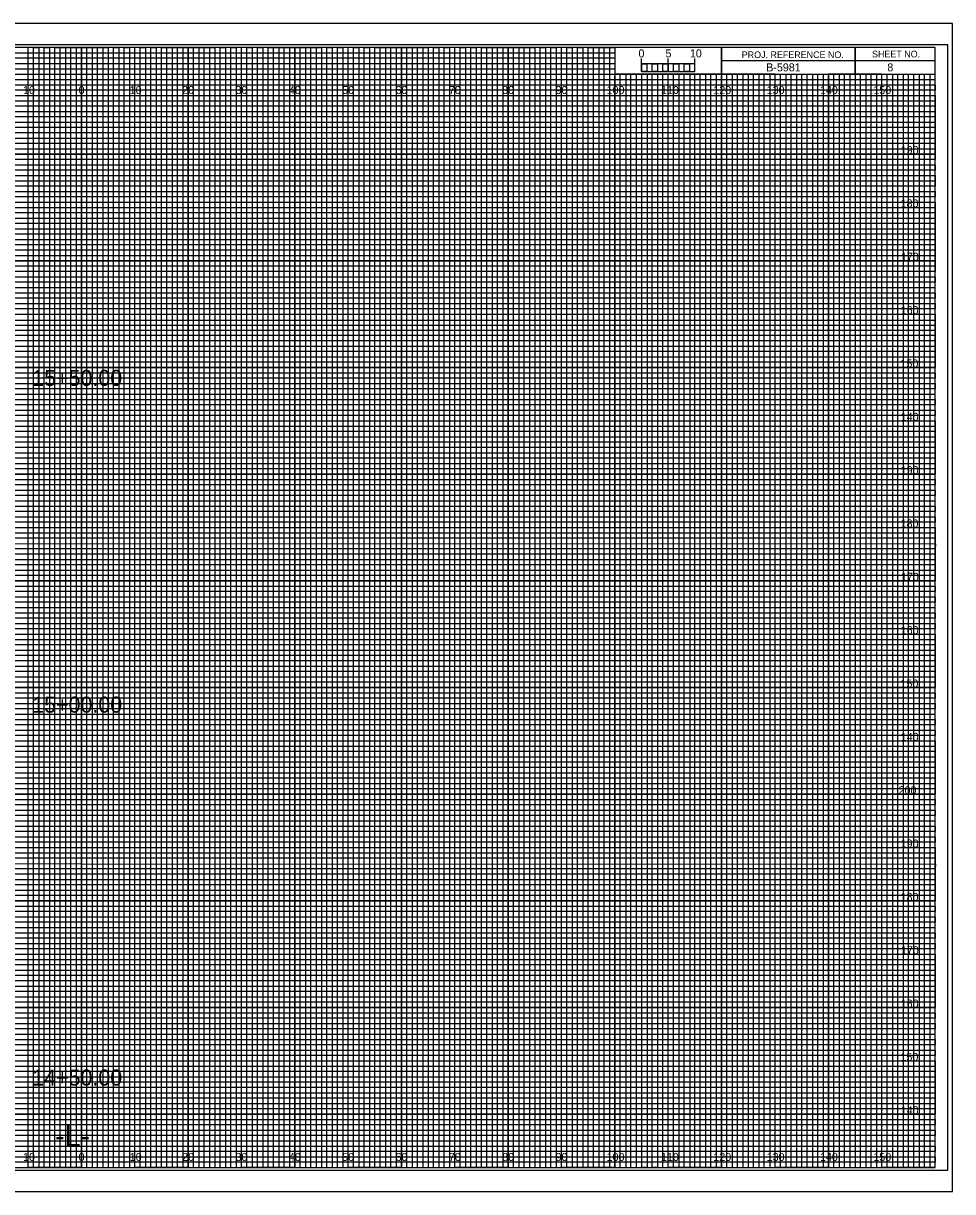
# Model space of a CAD drawing. Extents: x -13 to 323, y -5 to 4174.
# Drawn here: x 149.1 to 323.3, y 435.5 to 654.5 of the extents above; entities that cross this region are included whole.
import ezdxf

# ---------------------------------------------------------------- set-up
doc = ezdxf.new("R2010")
doc.units = 0
for name, color, linetype in [('Exist Cross Section Cell', 7, 'Continuous'), ('Exist XS Center Line Elevation Label', 7, 'Continuous'), ('Exist XS Ground Line', 7, 'Continuous'), ('Prop CMT Concrete Structures', 7, 'Continuous'), ('Prop CMT Guardrail Graphics', 7, 'Continuous'), ('Prop CMT Pvmt Course 1', 7, 'Continuous'), ('Prop CMT Pvmt Course 2', 7, 'Continuous'), ('Prop CMT Pvmt Course 3', 7, 'Continuous'), ('Prop CMT Pvmt Surface', 7, 'Continuous'), ('Prop CMT Shld Paved Course 1', 7, 'Continuous'), ('Prop CMT Shld Paved Course 2', 7, 'Continuous'), ('Prop CMT Shld Paved Course 3', 7, 'Continuous'), ('Prop CMT Subgrade Earthwork', 7, 'Continuous'), ('Prop XS Ditch Standard Text', 7, 'Continuous'), ('Prop XS SE Text', 7, 'Continuous'), ('Prop XS Side Slope Text', 7, 'Continuous'), ('Scratch_Level_0', 7, 'Continuous')]:
    doc.layers.add(name, color=color, linetype=linetype)

msp = doc.modelspace()

# ---------------------------------------------------------------- linework, layer by layer
at = {"layer": 'Exist XS Center Line Elevation Label'}
for points in [[(145, 440), (155, 440), (155, 650), (165, 650), (165, 440), (175, 440), (175, 650), (185, 650), (185, 440), (195, 440), (195, 650), (205, 650), (205, 440), (215, 440), (215, 650), (225, 650), (225, 440), (235, 440), (235, 650), (245, 650), (245, 440), (255, 440), (255, 650), (259.93, 650), (260, 650), (260, 645), (264.99, 645), (264.99, 440), (275, 440), (275, 645), (285, 645), (285, 440), (295, 440), (295, 645), (305, 645), (305, 440), (315, 440), (315, 645)], [(0, 645), (275, 645)], [(0, 625), (320, 625), (320, 635), (0, 635)], [(0, 605), (320, 605), (320, 615), (0, 615)], [(0, 585), (320, 585), (320, 595), (0, 595)], [(0, 565), (320, 565), (320, 575), (0, 575)], [(0, 545), (320, 545), (320, 555), (0, 555)], [(0, 525), (320, 525), (320, 535), (0, 535)], [(0, 505), (320, 505), (320, 515), (0, 515)], [(0, 485), (320, 485), (320, 495), (0, 495)], [(0, 465), (320, 465), (320, 475), (0, 475)], [(0, 445), (320, 445), (320, 455), (0, 455)]]:
    msp.add_lwpolyline(points, dxfattribs=at)
at = {"layer": 'Exist XS Ground Line'}
for p, q in [((150, 650), (140, 650)), ((150, 440), (150, 650)), ((170, 650), (160, 650)), ((160, 650), (160, 440)), ((170, 440), (170, 650)), ((190, 650), (180, 650)), ((180, 650), (180, 440)), ((190, 440), (190, 650)), ((210, 650), (200, 650)), ((200, 650), (200, 440)), ((210, 440), (210, 650)), ((230, 650), (220, 650)), ((220, 650), (220, 440)), ((230, 440), (230, 650)), ((250, 650), (240, 650)), ((240, 650), (240, 440)), ((250, 440), (250, 650)), ((260, 650), (260, 440)), ((270, 440), (270, 645)), ((290, 645), (280, 645)), ((280, 645), (280, 440)), ((290, 440), (290, 645)), ((310, 645), (300, 645)), ((300, 645), (300, 440)), ((310, 440), (310, 645)), ((160, 440), (150, 440)), ((180, 440), (170, 440)), ((200, 440), (190, 440)), ((220, 440), (210, 440)), ((240, 440), (230, 440)), ((260, 440), (250, 440)), ((280, 440), (270, 440)), ((300, 440), (290, 440)), ((320, 440), (310, 440)), ((320, 440), (320, 440))]:
    msp.add_line(p, q, dxfattribs=at)
for points in [[(0, 640), (320, 640), (320, 630), (0, 630)], [(0, 620), (320, 620), (320, 610), (0, 610)], [(0, 600), (320, 600), (320, 590), (0, 590)], [(0, 580), (320, 580), (320, 570), (0, 570)], [(0, 560), (320, 560), (320, 550), (0, 550)], [(0, 540), (320, 540), (320, 530), (0, 530)], [(0, 520), (320, 520), (320, 510), (0, 510)], [(0, 500), (320, 500), (320, 490), (0, 490)], [(0, 480), (320, 480), (320, 470), (0, 470)], [(0, 460), (320, 460), (320, 450), (0, 450)]]:
    msp.add_lwpolyline(points, dxfattribs=at)
at = {"layer": 'Prop CMT Pvmt Course 1'}
for p, q in [((323.3, 654.5), (-13.4, 654.5)), ((-13.4, 435.5), (323.3, 435.5))]:
    msp.add_line(p, q, dxfattribs=at)
at = {"layer": 'Prop CMT Pvmt Course 2'}
msp.add_lwpolyline([(-13.4, 435.5), (323.3, 435.5), (323.3, 654.5), (-13.4, 654.5)], close=True, dxfattribs=at)
at = {"layer": 'Prop CMT Pvmt Course 3'}
msp.add_lwpolyline([(-10.8, 439.5), (322.4, 439.5), (322.4, 650.5), (-10.8, 650.5)], close=True, dxfattribs=at)
at = {"layer": 'Prop CMT Shld Paved Course 1'}
for p, q in [((305, 650), (305, 645)), ((305, 645), (305, 650)), ((280, 647.5), (280, 645)), ((320, 647.49), (280, 647.49)), ((280, 645), (320, 645))]:
    msp.add_line(p, q, dxfattribs=at)
for points in [[(320, 650), (0, 650), (0, 440), (320, 440)], [(280, 650), (260, 650), (260, 645.03), (280, 645.03)], [(320, 650), (280, 650), (280, 645), (320, 645)]]:
    msp.add_lwpolyline(points, close=True, dxfattribs=at)
at = {"layer": 'Prop CMT Shld Paved Course 2'}
for p, q in [((267, 645), (266.01, 645)), ((266.01, 645), (266.01, 440)), ((267, 440), (267, 645)), ((269, 645), (268, 645)), ((268, 645), (268, 440)), ((269, 440), (269, 645)), ((266.01, 440), (265, 440)), ((268, 440), (267, 440))]:
    msp.add_line(p, q, dxfattribs=at)
for points in [[(150, 440), (151, 440), (151, 650), (152, 650), (152, 440)], [(152, 440), (153, 440), (153, 650), (154, 650), (154, 440)], [(155, 440), (156, 440), (156, 650), (157, 650), (157, 440)], [(157, 440), (158, 440), (158, 650), (159, 650), (159, 440)], [(160, 440), (161, 440), (161, 650), (162, 650), (162, 440)], [(162, 440), (163, 440), (163, 650), (164, 650), (164, 440)], [(165, 440), (166, 440), (166, 650), (167, 650), (167, 440)], [(167, 440), (168, 440), (168, 650), (169, 650), (169, 440)], [(170, 440), (171, 440), (171, 650), (172, 650), (172, 440)], [(172, 440), (173, 440), (173, 650), (174, 650), (174, 440)], [(175, 440), (176, 440), (176, 650), (177, 650), (177, 440)], [(177, 440), (178, 440), (178, 650), (179, 650), (179, 440)], [(180, 440), (181, 440), (181, 650), (182, 650), (182, 440)], [(182, 440), (183, 440), (183, 650), (184, 650), (184, 440)], [(185, 440), (186, 440), (186, 650), (187, 650), (187, 440)], [(187, 440), (188, 440), (188, 650), (189, 650), (189, 440)], [(190, 440), (191, 440), (191, 650), (192, 650), (192, 440)], [(192, 440), (193, 440), (193, 650), (194, 650), (194, 440)], [(195, 440), (196, 440), (196, 650), (197, 650), (197, 440)], [(197, 440), (198, 440), (198, 650), (199, 650), (199, 440)], [(200, 440), (201, 440), (201, 650), (202, 650), (202, 440)], [(202, 440), (203, 440), (203, 650), (204, 650), (204, 440)], [(205, 440), (206, 440), (206, 650), (207, 650), (207, 440)], [(207, 440), (208, 440), (208, 650), (209, 650), (209, 440)], [(210, 440), (211, 440), (211, 650), (212, 650), (212, 440)], [(212, 440), (213, 440), (213, 650), (214, 650), (214, 440)], [(215, 440), (216, 440), (216, 650), (217, 650), (217, 440)], [(217, 440), (218, 440), (218, 650), (219, 650), (219, 440)], [(220, 440), (221, 440), (221, 650), (222, 650), (222, 440)], [(222, 440), (223, 440), (223, 650), (224, 650), (224, 440)], [(225, 440), (226, 440), (226, 650), (227, 650), (227, 440)], [(227, 440), (228, 440), (228, 650), (229, 650), (229, 440)], [(230, 440), (231, 440), (231, 650), (232, 650), (232, 440)], [(232, 440), (233, 440), (233, 650), (234, 650), (234, 440)], [(235, 440), (236, 440), (236, 650), (237, 650), (237, 440)], [(237, 440), (238, 440), (238, 650), (239, 650), (239, 440)], [(240, 440), (241, 440), (241, 650), (242, 650), (242, 440)], [(242, 440), (243, 440), (243, 650), (244, 650), (244, 440)], [(245, 440), (246, 440), (246, 650), (247, 650), (247, 440)], [(247, 440), (248, 440), (248, 650), (249, 650), (249, 440)], [(250, 440), (251, 440), (251, 650), (252, 650), (252, 440)], [(252, 440), (253, 440), (253, 650), (254, 650), (254, 440)], [(255, 440), (256, 440), (256, 650), (257, 650), (257, 440)], [(257, 440), (258, 440), (258, 650), (259, 650), (259, 440)], [(260, 440), (261, 440), (261, 645), (262.02, 645), (262.02, 440)], [(262, 440), (263, 440), (263, 645), (263.99, 645), (263.99, 440)], [(270, 440), (270.98, 440), (270.98, 645), (272, 645), (272, 440)], [(272, 440), (273, 440), (273, 645), (274.05, 645), (274.05, 440)], [(275, 440), (276, 440), (276, 645), (277, 645), (277, 440)], [(277, 440), (278, 440), (278, 645), (279, 645), (279, 440)], [(280, 440), (281, 440), (281, 645), (282, 645), (282, 440)], [(282, 440), (283, 440), (283, 645), (284, 645), (284, 440)], [(285, 440), (286, 440), (286, 645), (287, 645), (287, 440)], [(287, 440), (288, 440), (288, 645), (289, 645), (289, 440)], [(290, 440), (291, 440), (291, 645), (292, 645), (292, 440)], [(292, 440), (293, 440), (293, 645), (294, 645), (294, 440)], [(295, 440), (296, 440), (296, 645), (297, 645), (297, 440)], [(297, 440), (298, 440), (298, 645), (299, 645), (299, 440)], [(300, 440), (301, 440), (301, 645), (302, 645), (302, 440)], [(302, 440), (303, 440), (303, 645), (304, 645), (304, 440)], [(305, 440), (306, 440), (306, 645), (307, 645), (307, 440)], [(307, 440), (308, 440), (308, 645), (309, 645), (309, 440)], [(310, 440), (311, 440), (311, 645), (312, 645), (312, 440)], [(312, 440), (313, 440), (313, 645), (314, 645), (314, 440)], [(315, 440), (316, 440), (316, 645), (317, 645), (317, 440)], [(317, 440), (318, 440), (318, 645), (319, 645), (319, 440)]]:
    msp.add_lwpolyline(points, dxfattribs=at)
at = {"layer": 'Prop CMT Shld Paved Course 3'}
for p, q in [((265, 645.49), (265, 647.9)), ((265, 646.9), (265, 647.9)), ((270, 645.49), (270, 647.9)), ((275, 645.49), (275, 647.9)), ((275, 646.9), (275, 647.9))]:
    msp.add_line(p, q, dxfattribs=at)
for points in [[(275, 646.9), (265, 646.9), (265, 645.49), (275, 645.49)], [(265, 646.9), (266, 646.9), (266, 645.49), (265, 645.49)], [(267, 646.9), (268, 646.9), (268, 645.49), (267, 645.49)], [(269, 646.9), (270, 646.9), (270, 645.49), (269, 645.49)], [(271, 646.9), (272, 646.9), (272, 645.49), (271, 645.49)], [(273, 646.9), (274, 646.9), (274, 645.49), (273, 645.49)]]:
    msp.add_lwpolyline(points, close=True, dxfattribs=at)
at = {"layer": 'Prop CMT Subgrade Earthwork'}
for p, q in [((150, 440), (150, 650)), ((160, 440), (160, 650)), ((170, 440), (170, 650)), ((180, 440), (180, 650)), ((190, 440), (190, 650)), ((200, 440), (200, 650)), ((210, 440), (210, 650)), ((220, 440), (220, 650)), ((230, 440), (230, 650)), ((240, 440), (240, 650)), ((250, 440), (250, 650)), ((260, 440), (260, 644.69)), ((270, 440), (270, 644.69)), ((280, 440), (280, 644.69)), ((290, 440), (290, 644.69)), ((300, 440), (300, 644.69)), ((310, 440), (310, 644.69)), ((0, 640), (320, 640)), ((0, 630), (320, 630)), ((0, 620), (320, 620)), ((0, 610), (320, 610)), ((0, 600), (320, 600)), ((0, 590), (320, 590)), ((0, 580), (320, 580)), ((0, 570), (320, 570)), ((0, 560), (320, 560)), ((0, 550), (320, 550)), ((0, 540), (320, 540)), ((0, 530), (320, 530)), ((0, 520), (320, 520)), ((0, 510), (320, 510)), ((0, 500), (320, 500)), ((0, 490), (320, 490)), ((0, 480), (320, 480)), ((0, 470), (320, 470)), ((0, 460), (320, 460)), ((0, 450), (320, 450))]:
    msp.add_line(p, q, dxfattribs=at)
at = {"layer": 'Scratch_Level_0'}
for p, q in [((0, 649), (260, 649)), ((260, 649), (260, 647.98)), ((260, 647.98), (0, 647.98)), ((0, 647), (260, 647)), ((260, 647), (260, 645.89)), ((260, 645.89), (0, 645.89)), ((0, 644), (320, 644))]:
    msp.add_line(p, q, dxfattribs=at)
for points in [[(0, 643), (270, 643), (320, 643), (320, 642), (0, 642)], [(0, 641), (320, 641), (320, 639), (0, 639)], [(0, 638), (320, 638), (320, 637), (0, 636.98)], [(0, 636), (320, 636), (320, 634), (0, 634)], [(0, 633), (320, 633), (320, 632), (0, 632)], [(0, 631), (320, 631), (320, 629), (0, 629)], [(0, 628), (320, 628), (320, 627), (0, 627)], [(0, 626), (320, 626), (320, 624), (0, 624)], [(0, 623), (320, 623), (320, 622), (0, 622)], [(0, 621), (320, 621), (320, 619), (0, 619)], [(0, 618), (320, 618), (320, 617), (0, 617)], [(0, 616), (320, 616), (320, 613.95), (320, 613), (320, 612), (0, 612)], [(0, 614), (320, 614), (320, 613), (0, 613)], [(0, 611), (320, 611), (320, 609), (0, 609.03)], [(0, 609.03), (320, 609), (320, 608), (0, 608)], [(0, 607), (320, 607), (320, 606), (0, 606)], [(0, 604), (320, 604), (320, 603), (0, 603)], [(0, 602), (320, 602), (320, 601), (0, 601)], [(-0.07, 598.89), (320, 598.89), (320, 597.88), (-0.07, 597.88)], [(0, 597), (320, 597), (320, 596), (0, 596)], [(0, 594), (320, 594), (320, 593), (0, 593)], [(0, 592), (320, 592), (320, 591), (0, 591)], [(0, 589), (320, 589), (320, 588), (0, 588)], [(0, 587), (320, 587), (320, 586), (0, 586)], [(0, 584), (320, 584), (320, 583), (0, 583)], [(0, 582), (320, 582), (320, 581), (0, 581)], [(0, 579), (320, 579), (319.99, 577.98), (0, 578)], [(0, 577), (320, 577), (320, 576), (0, 576)], [(0, 574), (320, 574), (320, 573), (0, 573)], [(0, 572), (320, 572), (320, 571), (0, 571)], [(0, 569), (320, 569), (320, 568), (0, 568)], [(0, 567), (320, 567), (320, 566), (0, 566)], [(0, 564), (320, 564), (320, 563), (0, 563)], [(0, 562), (320, 562), (320, 561), (0, 561)], [(0, 559), (320, 559), (320, 558), (0, 558)], [(0, 556.99), (320.07, 556.91), (320, 556), (0, 556)], [(0, 554), (320, 554), (320, 553), (0, 553)], [(0, 552), (320, 552), (320, 551), (0, 551)], [(0, 549), (320, 549), (320, 548), (0, 548)], [(0, 547), (320, 547), (320, 546), (0, 546)], [(0, 544), (320, 544), (320, 543), (0, 543)], [(0, 542), (320, 542), (320, 541), (0, 541)], [(0, 539), (320, 539), (320, 538), (0, 538)], [(0, 537), (320, 537), (320, 536), (0, 536)], [(0, 534), (320, 534), (320, 533), (0, 533)], [(0, 532), (320, 532), (320, 531), (0, 531)], [(0, 529), (320, 529), (320, 528), (0, 528)], [(0, 527), (320, 527), (320, 526), (0, 526)], [(0, 524), (320, 524), (320, 523), (0, 523)], [(0, 522), (320, 522), (320, 521), (0, 521)], [(0, 519), (320, 519), (319.99, 517.98), (0, 518)], [(0, 517), (320, 517), (320, 516), (0, 516)], [(0, 514), (320, 514), (320, 513), (0, 513)], [(0, 512), (320, 512), (320, 511), (0, 511)], [(0, 509), (320, 509), (320, 508), (0, 508)], [(0, 507), (320, 507), (320, 506), (0, 506)], [(0, 504), (320, 504), (320, 503), (0, 503)], [(0, 502), (320, 502), (320, 501), (0, 501)], [(0, 499), (320, 499), (320, 498), (0, 498)], [(0, 496.99), (320.07, 496.91), (320, 496), (0, 496)], [(0, 494), (320, 494), (320, 493), (0, 493)], [(0, 492), (320, 492), (320, 491), (0, 491)], [(0, 489), (320, 489), (320, 488), (0, 488)], [(0, 487), (320, 487), (320, 486), (0, 486)], [(0, 484), (320, 484), (320, 483), (0, 483)], [(0, 482), (320, 482), (320, 481), (0, 481)], [(0, 479), (320, 479), (320, 478), (0, 478)], [(0, 477), (320, 477), (320, 476), (0, 476)], [(0, 474), (320, 474), (320, 473), (0, 473)], [(0, 472), (320, 472), (320, 471), (0, 471)], [(0, 469), (320, 469), (320, 468), (0, 468)], [(0, 467), (320, 467), (320, 466), (0, 466)], [(0, 464), (320, 464), (320, 463), (0, 463)], [(0, 462), (320, 462), (320, 461), (0, 461)], [(0, 459), (320, 459), (320, 458), (0, 458)], [(0, 457), (320, 457), (320, 456), (0, 456)], [(0, 454), (320, 454), (320, 453), (0, 453)], [(0, 452), (320, 452), (320, 451), (0, 451)], [(0, 449), (320, 449), (320, 448), (0, 448)], [(0, 447), (320, 447), (320, 446), (0, 446)], [(0, 444), (320, 444), (320, 443), (0, 443)], [(0, 442), (320, 442), (320, 441), (0, 441)]]:
    msp.add_lwpolyline(points, dxfattribs=at)

# ---------------------------------------------------------------- texts
at = {"layer": 'Exist Cross Section Cell'}
for s, p in [('10', (149.04, 641.25)), ('0', (159.45, 641.25)), ('0', (159.45, 641.25)), ('10', (169.04, 641.25)), ('20', (178.86, 641.25)), ('30', (188.86, 641.25)), ('40', (198.86, 641.25)), ('50', (208.86, 641.25)), ('60', (218.86, 641.25)), ('70', (228.86, 641.25)), ('80', (238.86, 641.25)), ('90', (248.86, 641.25)), ('100', (258.44, 641.25)), ('110', (268.62, 641.25)), ('120', (278.44, 641.25)), ('130', (288.44, 641.25)), ('140', (298.44, 641.25)), ('150', (308.44, 641.25)), ('10', (149.04, 441.25)), ('0', (159.45, 441.25)), ('0', (159.45, 441.25)), ('10', (169.04, 441.25)), ('20', (178.86, 441.25)), ('30', (188.86, 441.25)), ('40', (198.86, 441.25)), ('50', (208.86, 441.25)), ('60', (218.86, 441.25)), ('70', (228.86, 441.25)), ('80', (238.86, 441.25)), ('90', (248.86, 441.25)), ('100', (258.44, 441.25)), ('110', (268.62, 441.25)), ('120', (278.44, 441.25)), ('130', (288.44, 441.25)), ('140', (298.44, 441.25)), ('150', (308.44, 441.25))]:
    msp.add_text(s, height=1.5, dxfattribs=at).set_placement(p)
at = {"layer": 'Prop CMT Concrete Structures'}
for s, p in [('15+50.00', (150.77, 586.54)), ('15+00.00', (150.77, 525.29)), ('14+50.00', (150.77, 455.39))]:
    msp.add_text(s, height=3, dxfattribs=at).set_placement(p)
at = {"layer": 'Prop CMT Guardrail Graphics'}
for s, p in [('190', (313.57, 630)), ('180', (313.55, 620)), ('170', (313.61, 610)), ('160', (313.57, 600)), ('150', (313.52, 590)), ('140', (313.57, 580)), ('190', (313.57, 570)), ('180', (313.55, 560)), ('170', (313.61, 550)), ('160', (313.57, 540)), ('150', (313.52, 530)), ('140', (313.57, 520)), ('200', (313.17, 510)), ('190', (313.57, 500)), ('180', (313.55, 490)), ('170', (313.61, 480)), ('160', (313.57, 470)), ('150', (313.52, 460)), ('140', (313.57, 450))]:
    msp.add_text(s, height=1.5, dxfattribs=at).set_placement(p)
at = {"layer": 'Prop CMT Pvmt Surface'}
for s, p in [('5', (269.47, 648.12)), ('10', (274.04, 648.12))]:
    msp.add_text(s, height=1.5, dxfattribs=at).set_placement(p)
at = {"layer": 'Prop CMT Shld Paved Course 1'}
for s, p in [('PROJ. REFERENCE NO.', (283.77, 647.99)), ('SHEET NO.', (308.19, 648.12))]:
    msp.add_text(s, height=1.25, dxfattribs=at).set_placement(p)
at = {"layer": 'Prop CMT Shld Paved Course 3'}
msp.add_text('0', height=1.5, dxfattribs=at).set_placement((264.41, 648.12))
at = {"layer": 'Prop XS Ditch Standard Text'}
msp.add_text('-L-', height=4, dxfattribs=at).set_placement((155.06, 444))
at = {"layer": 'Prop XS SE Text'}
msp.add_text(' B-5981', height=1.5, dxfattribs=at).set_placement((287.79, 645.5))
at = {"layer": 'Prop XS Side Slope Text'}
msp.add_text('8', height=1.5, dxfattribs=at).set_placement((311.06, 645.5))

doc.saveas('drawing.dxf')
